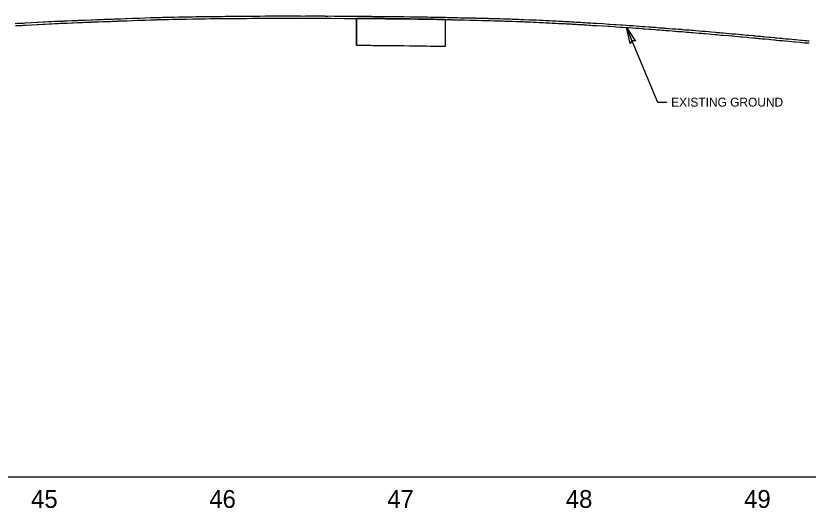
# Model space of a CAD drawing. Extents: x 2115752 to 2121174, y 562881 to 567245.
# Drawn here: x 2120180.3 to 2120624.7, y 566358.2 to 566634.2 of the extents above; entities that cross this region are included whole.
import ezdxf

# ---------------------------------------------------------------- set-up
doc = ezdxf.new("R2010")
doc.units = 0
for name, color, linetype in [('Exist Profile Cell', 7, 'Continuous'), ('Exist Vertical Profile Ground Line', 7, 'Continuous'), ('Exist Vertical Profile Horizontal Axis Label Major', 7, 'Continuous'), ('Prop Terminator CELL', 7, 'Continuous'), ('Prop VPI Label', 7, 'Continuous'), ('Prop XS Undercut Exc', 7, 'Continuous'), ('Prop XS Undercut Exc Hatch', 7, 'Continuous'), ('Scratch_Level_1', 7, 'Continuous')]:
    doc.layers.add(name, color=color, linetype=linetype)

msp = doc.modelspace()

# ---------------------------------------------------------------- linework, layer by layer
at = {"layer": 'Exist Profile Cell'}
msp.add_line((2116696.3, 566375.81), (2121174.42, 566375.81), dxfattribs=at)
at = {"layer": 'Exist Vertical Profile Ground Line'}
for points in [[(2120180.06, 566628.67), (2120181.26, 566628.75), (2120181.79, 566628.77), (2120182.24, 566628.8), (2120183.67, 566628.84), (2120184.47, 566628.91), (2120185.35, 566628.98), (2120185.71, 566629), (2120189.09, 566629.19), (2120192.3, 566629.36), (2120192.82, 566629.39), (2120195.67, 566629.54), (2120196.52, 566629.58), (2120198.92, 566629.7), (2120199.7, 566629.73), (2120200.22, 566629.76), (2120202.25, 566629.85), (2120203.11, 566629.89), (2120203.96, 566629.92), (2120205.58, 566629.98), (2120206.67, 566630.02), (2120207.31, 566630.06), (2120207.93, 566630.09), (2120209.06, 566630.13), (2120211.76, 566630.27), (2120212.38, 566630.29), (2120214.93, 566630.4), (2120215.74, 566630.44), (2120217.74, 566630.52), (2120219.2, 566630.57), (2120222.54, 566630.71), (2120222.91, 566630.73), (2120225.72, 566630.83), (2120226.17, 566630.85), (2120226.6, 566630.87), (2120229.03, 566630.95), (2120229.66, 566630.97), (2120230.35, 566631), (2120232.34, 566631.07), (2120233.18, 566631.09), (2120234.28, 566631.14), (2120235.66, 566631.19), (2120237.77, 566631.27), (2120238.08, 566631.29), (2120238.66, 566631.3), (2120239.1, 566631.32), (2120241.87, 566631.42), (2120242.47, 566631.44), (2120245.84, 566631.56), (2120248.68, 566631.67), (2120249.22, 566631.69), (2120253, 566631.8), (2120255.81, 566631.9), (2120256.18, 566631.92), (2120256.62, 566631.93), (2120259.27, 566632.02), (2120259.74, 566632.03), (2120260.62, 566632.06), (2120261.67, 566632.07), (2120262.5, 566632.11), (2120263.28, 566632.13), (2120264.26, 566632.15), (2120265.17, 566632.15), (2120265.89, 566632.18), (2120268.23, 566632.23), (2120269.18, 566632.24), (2120271.77, 566632.3), (2120272.65, 566632.31), (2120275.47, 566632.37), (2120276.03, 566632.37), (2120279.42, 566632.43), (2120281.29, 566632.47), (2120282.92, 566632.5), (2120283.46, 566632.5), (2120286.61, 566632.55), (2120289.41, 566632.59), (2120290.35, 566632.6), (2120291.08, 566632.6)], [(2120291.08, 566632.6), (2120292.84, 566632.61), (2120293.44, 566632.62), (2120294.07, 566632.62), (2120296.25, 566632.64), (2120297.8, 566632.65), (2120298.69, 566632.65), (2120299.53, 566632.65), (2120301.55, 566632.67), (2120302.96, 566632.67), (2120305.26, 566632.69), (2120306.31, 566632.7), (2120308.94, 566632.74), (2120309.71, 566632.75), (2120312.65, 566632.78), (2120313.11, 566632.79), (2120313.92, 566632.8), (2120316.47, 566632.82), (2120317.2, 566632.83), (2120320.13, 566632.85), (2120321.53, 566632.85), (2120323.21, 566632.85), (2120323.86, 566632.85), (2120326.57, 566632.85), (2120327.65, 566632.86), (2120329.15, 566632.87), (2120329.9, 566632.87), (2120331.36, 566632.92), (2120333.39, 566632.91), (2120335.14, 566632.87), (2120336.69, 566632.88), (2120338.87, 566632.88), (2120340.08, 566632.86), (2120341.2, 566632.83), (2120342.58, 566632.85), (2120343.5, 566632.86), (2120346.12, 566632.85), (2120346.91, 566632.85), (2120349.59, 566632.86), (2120350.24, 566632.87), (2120351.9, 566632.85), (2120353.42, 566632.84), (2120353.73, 566632.83), (2120355.33, 566632.79), (2120357.11, 566632.84), (2120358.83, 566632.76), (2120360.84, 566632.81), (2120362.38, 566632.74), (2120363.79, 566632.78), (2120364.72, 566632.77), (2120365.92, 566632.72), (2120367.11, 566632.75), (2120368.56, 566632.74), (2120369.52, 566632.7), (2120370.61, 566632.71), (2120372.28, 566632.69), (2120373.94, 566632.68), (2120376, 566632.68), (2120377.34, 566632.67), (2120379.7, 566632.65), (2120380.78, 566632.63), (2120381.96, 566632.6), (2120383.35, 566632.62), (2120384.25, 566632.62), (2120386.96, 566632.59), (2120387.55, 566632.58), (2120390.41, 566632.57), (2120390.94, 566632.56), (2120392.58, 566632.52), (2120394.36, 566632.53), (2120395.5, 566632.52), (2120397.98, 566632.49), (2120401.67, 566632.45), (2120403.07, 566632.38), (2120404.45, 566632.41), (2120405.63, 566632.4), (2120407.82, 566632.36), (2120409.36, 566632.34), (2120411.19, 566632.29), (2120413.06, 566632.25), (2120414.58, 566632.22), (2120416.78, 566632.2), (2120417.9, 566632.18), (2120420.47, 566632.12), (2120420.92, 566632.1), (2120421.33, 566632.1), (2120422.64, 566632.04), (2120424.2, 566632.03), (2120424.75, 566632.02), (2120426.14, 566631.96), (2120428.16, 566631.96), (2120429.67, 566631.88), (2120431.78, 566631.87), (2120434.81, 566631.78), (2120435.35, 566631.77), (2120438.18, 566631.72), (2120439.08, 566631.7), (2120441.6, 566631.63), (2120442.69, 566631.6), (2120445.01, 566631.54), (2120445.58, 566631.53)], [(2120445.58, 566631.53), (2120446.27, 566631.51), (2120448.43, 566631.44), (2120449.1, 566631.41), (2120449.98, 566631.41), (2120451.02, 566631.37), (2120451.86, 566631.38), (2120453.66, 566631.33), (2120454.5, 566631.28), (2120455.22, 566631.26), (2120457.47, 566631.2), (2120458.65, 566631.15), (2120461.11, 566631.07), (2120461.92, 566631.04), (2120463.41, 566630.91), (2120464.74, 566630.91), (2120465.35, 566630.89), (2120468.34, 566630.76), (2120468.75, 566630.74), (2120470.44, 566630.61), (2120472.1, 566630.6), (2120474, 566630.45), (2120475.82, 566630.42), (2120477.57, 566630.28), (2120479.19, 566630.26), (2120479.55, 566630.25), (2120481.09, 566630.12), (2120482.32, 566630.1), (2120482.7, 566630.08), (2120483.23, 566630.06), (2120484.61, 566629.96), (2120485.71, 566629.94), (2120486.29, 566629.91), (2120487.03, 566629.88), (2120488.15, 566629.8), (2120489.06, 566629.78), (2120489.83, 566629.72), (2120490.81, 566629.68), (2120491.75, 566629.61), (2120492.47, 566629.58), (2120493.38, 566629.51), (2120494.5, 566629.45), (2120495.29, 566629.39), (2120495.91, 566629.37), (2120496.93, 566629.3), (2120498.25, 566629.24), (2120498.83, 566629.19), (2120499.29, 566629.17), (2120500.45, 566629.05), (2120502.02, 566629.01), (2120502.66, 566628.97), (2120503.98, 566628.84), (2120505.99, 566628.76), (2120509.61, 566628.54), (2120512.75, 566628.33), (2120513.21, 566628.31), (2120516.14, 566628.12), (2120516.86, 566628.08), (2120519.51, 566627.88), (2120520.56, 566627.82), (2120522.89, 566627.66), (2120524.21, 566627.57), (2120526.27, 566627.43), (2120528.14, 566627.28), (2120529.68, 566627.17), (2120531.51, 566627.04), (2120532.33, 566626.95), (2120533.09, 566626.91), (2120535.3, 566626.75), (2120535.89, 566626.7), (2120536.45, 566626.66), (2120538.91, 566626.48), (2120539.81, 566626.41), (2120541.27, 566626.26), (2120542.6, 566626.19), (2120543.21, 566626.14), (2120543.65, 566626.1), (2120544.81, 566625.98), (2120546.48, 566625.9), (2120548.38, 566625.69), (2120549.97, 566625.62), (2120550.31, 566625.59), (2120551.4, 566625.47), (2120551.86, 566625.42), (2120553.33, 566625.36), (2120553.94, 566625.31), (2120555.37, 566625.15), (2120556.65, 566625.09), (2120557.84, 566624.99), (2120559.15, 566624.88), (2120560.04, 566624.81), (2120561.42, 566624.7), (2120563.41, 566624.53), (2120565.07, 566624.4), (2120565.95, 566624.3), (2120566.91, 566624.24), (2120568.95, 566624.07), (2120570.18, 566623.96), (2120572.55, 566623.76), (2120573.47, 566623.67), (2120574.75, 566623.53)], [(2120574.75, 566623.53), (2120576.15, 566623.43), (2120576.53, 566623.39), (2120576.88, 566623.36), (2120580.22, 566623.07), (2120581.94, 566622.93), (2120582.42, 566622.88), (2120583.72, 566622.77), (2120585.5, 566622.56), (2120586.86, 566622.47), (2120587.73, 566622.39), (2120590.26, 566622.17), (2120591.46, 566622.07), (2120593.66, 566621.85), (2120594.3, 566621.77), (2120595.16, 566621.71), (2120596.16, 566621.6), (2120597.01, 566621.54), (2120597.92, 566621.44), (2120598.96, 566621.37), (2120599.71, 566621.3), (2120600.38, 566621.24), (2120602.67, 566621.02), (2120603.79, 566620.91), (2120605.68, 566620.73), (2120606.27, 566620.67), (2120606.97, 566620.61), (2120608.46, 566620.42), (2120610.02, 566620.33), (2120610.35, 566620.3), (2120612.02, 566620.1), (2120613.83, 566619.98), (2120617.1, 566619.67), (2120617.58, 566619.63), (2120620.46, 566619.35), (2120621.26, 566619.28), (2120622.57, 566619.12), (2120623.85, 566619.03), (2120624.5, 566618.97), (2120625.07, 566618.92)]]:
    msp.add_lwpolyline(points, dxfattribs=at)
at = {"layer": 'Prop Terminator CELL'}
msp.add_lwpolyline([(2120524.92, 566618.75), (2120522.89, 566627.66), (2120527.85, 566619.92), (2120525.93, 566620.36)], close=True, dxfattribs=at)
at = {"layer": 'Prop VPI Label'}
msp.add_lwpolyline([(2120545.42, 566585.52), (2120540.45, 566585.52), (2120522.89, 566627.66)], dxfattribs=at)
at = {"layer": 'Prop XS Undercut Exc'}
for p, q in [((2120371.3, 566617.69), (2120371.3, 566632.7)), ((2120421.3, 566617.09), (2120421.3, 566632.1))]:
    msp.add_line(p, q, dxfattribs=at)
msp.add_lwpolyline([(2120371.3, 566617.69), (2120375.96, 566617.68), (2120377.23, 566617.67), (2120379.49, 566617.65), (2120380.45, 566617.63), (2120381.88, 566617.59), (2120383.49, 566617.62), (2120384.17, 566617.62), (2120386.8, 566617.59), (2120387.42, 566617.58), (2120390.29, 566617.57), (2120390.67, 566617.56), (2120392.44, 566617.52), (2120394.34, 566617.53), (2120395.33, 566617.52), (2120397.79, 566617.49), (2120401.22, 566617.45), (2120402.86, 566617.37), (2120404.55, 566617.4), (2120405.44, 566617.4), (2120407.6, 566617.36), (2120409.09, 566617.34), (2120410.84, 566617.3), (2120412.72, 566617.26), (2120414.32, 566617.22), (2120416.58, 566617.2), (2120417.6, 566617.18), (2120421.3, 566617.09)], dxfattribs=at)
at = {"layer": 'Prop XS Undercut Exc Hatch'}
for p, q in [((2120371.3, 566632.7), (2120371.3, 566617.69)), ((2120421.3, 566632.1), (2120420.92, 566632.1)), ((2120421.3, 566617.09), (2120421.3, 566632.1))]:
    msp.add_line(p, q, dxfattribs=at)
for points in [[(2120420.92, 566632.1), (2120420.47, 566632.12), (2120417.9, 566632.18), (2120416.78, 566632.2), (2120414.58, 566632.22), (2120413.06, 566632.25), (2120411.19, 566632.29), (2120409.36, 566632.34), (2120407.82, 566632.36), (2120405.63, 566632.4), (2120404.45, 566632.41), (2120403.07, 566632.38), (2120401.67, 566632.45), (2120397.98, 566632.49), (2120395.5, 566632.52), (2120394.36, 566632.53), (2120392.58, 566632.52), (2120390.94, 566632.56), (2120390.41, 566632.57), (2120387.55, 566632.58), (2120386.96, 566632.59), (2120384.25, 566632.62), (2120383.35, 566632.62), (2120381.96, 566632.6), (2120380.78, 566632.63), (2120379.7, 566632.65), (2120377.34, 566632.67), (2120376, 566632.68), (2120373.94, 566632.68), (2120372.28, 566632.69), (2120371.3, 566632.7)], [(2120371.3, 566617.69), (2120375.96, 566617.68), (2120377.23, 566617.67), (2120379.49, 566617.65), (2120380.45, 566617.63), (2120381.88, 566617.59), (2120383.49, 566617.62), (2120384.17, 566617.62), (2120386.8, 566617.59), (2120387.42, 566617.58), (2120390.29, 566617.57), (2120390.67, 566617.56), (2120392.44, 566617.52), (2120394.34, 566617.53), (2120395.33, 566617.52), (2120397.79, 566617.49), (2120401.22, 566617.45), (2120402.86, 566617.37), (2120404.55, 566617.4), (2120405.44, 566617.4), (2120407.6, 566617.36), (2120409.09, 566617.34), (2120410.84, 566617.3), (2120412.72, 566617.26), (2120414.32, 566617.22), (2120416.58, 566617.2), (2120417.6, 566617.18), (2120421.3, 566617.09)]]:
    msp.add_lwpolyline(points, dxfattribs=at)
at = {"layer": 'Scratch_Level_1'}
for points in [[(2120179.98, 566629.92), (2120181.21, 566630), (2120181.73, 566630.02), (2120182.17, 566630.05), (2120183.6, 566630.09), (2120184.37, 566630.15), (2120185.27, 566630.23), (2120185.64, 566630.25), (2120189.02, 566630.44), (2120192.23, 566630.61), (2120192.76, 566630.64), (2120195.6, 566630.78), (2120196.45, 566630.83), (2120198.86, 566630.94), (2120199.64, 566630.98), (2120200.16, 566631.01), (2120202.2, 566631.1), (2120203.06, 566631.14), (2120203.91, 566631.17), (2120205.54, 566631.23), (2120206.62, 566631.27), (2120207.25, 566631.3), (2120207.87, 566631.34), (2120209, 566631.38), (2120211.7, 566631.51), (2120212.32, 566631.54), (2120214.87, 566631.65), (2120215.69, 566631.69), (2120217.69, 566631.77), (2120219.15, 566631.82), (2120222.49, 566631.96), (2120222.87, 566631.98), (2120225.67, 566632.08), (2120226.12, 566632.1), (2120226.56, 566632.11), (2120228.98, 566632.2), (2120229.61, 566632.22), (2120230.29, 566632.25), (2120232.3, 566632.32), (2120233.14, 566632.34), (2120234.23, 566632.39), (2120235.61, 566632.44), (2120237.72, 566632.52), (2120238.05, 566632.53), (2120238.62, 566632.55), (2120239.04, 566632.57), (2120241.82, 566632.67), (2120242.43, 566632.69), (2120245.8, 566632.81), (2120248.64, 566632.92), (2120249.18, 566632.93), (2120252.96, 566633.04), (2120255.76, 566633.15), (2120256.13, 566633.17), (2120256.58, 566633.18), (2120259.23, 566633.27), (2120259.7, 566633.28), (2120260.59, 566633.31), (2120261.63, 566633.32), (2120262.46, 566633.36), (2120263.25, 566633.38), (2120264.25, 566633.4), (2120265.15, 566633.4), (2120265.85, 566633.43), (2120268.21, 566633.47), (2120269.15, 566633.49), (2120271.75, 566633.55), (2120272.62, 566633.56), (2120275.45, 566633.61), (2120276.01, 566633.62), (2120279.4, 566633.68), (2120281.26, 566633.72), (2120282.9, 566633.74), (2120283.44, 566633.75), (2120286.59, 566633.8), (2120289.39, 566633.84), (2120290.33, 566633.85), (2120291.07, 566633.85)], [(2120291.07, 566633.85), (2120292.83, 566633.86), (2120293.43, 566633.87), (2120294.06, 566633.87), (2120296.24, 566633.89), (2120297.8, 566633.9), (2120298.69, 566633.9), (2120299.52, 566633.9), (2120301.54, 566633.92), (2120302.96, 566633.92), (2120305.25, 566633.94), (2120306.29, 566633.95), (2120308.92, 566633.99), (2120309.7, 566634), (2120312.64, 566634.03), (2120313.1, 566634.04), (2120313.91, 566634.05), (2120316.46, 566634.07), (2120317.19, 566634.08), (2120320.12, 566634.1), (2120321.54, 566634.1), (2120323.21, 566634.1), (2120323.86, 566634.1), (2120326.56, 566634.1), (2120327.64, 566634.11), (2120329.14, 566634.12), (2120329.88, 566634.12), (2120331.35, 566634.17), (2120333.4, 566634.16), (2120335.15, 566634.12), (2120336.68, 566634.13), (2120338.88, 566634.13), (2120340.11, 566634.11), (2120341.21, 566634.08), (2120342.57, 566634.1), (2120343.5, 566634.11), (2120346.12, 566634.1), (2120346.91, 566634.1), (2120349.58, 566634.11), (2120350.24, 566634.12), (2120351.91, 566634.1), (2120353.43, 566634.09), (2120353.76, 566634.08), (2120355.33, 566634.04), (2120357.12, 566634.09), (2120358.84, 566634.01), (2120360.85, 566634.06), (2120362.39, 566633.99), (2120363.78, 566634.03), (2120364.75, 566634.02), (2120365.93, 566633.97), (2120367.1, 566634), (2120368.6, 566633.99), (2120369.54, 566633.95), (2120370.61, 566633.96), (2120372.29, 566633.94), (2120373.95, 566633.93), (2120376.01, 566633.93), (2120377.35, 566633.92), (2120379.72, 566633.9), (2120380.81, 566633.88), (2120381.97, 566633.85), (2120383.34, 566633.87), (2120384.26, 566633.87), (2120386.97, 566633.84), (2120387.56, 566633.83), (2120390.42, 566633.82), (2120390.96, 566633.81), (2120392.59, 566633.77), (2120394.36, 566633.78), (2120395.52, 566633.77), (2120398, 566633.74), (2120401.7, 566633.69), (2120403.09, 566633.63), (2120404.45, 566633.66), (2120405.65, 566633.65), (2120407.84, 566633.61), (2120409.39, 566633.59), (2120411.22, 566633.54), (2120413.08, 566633.5), (2120414.6, 566633.47), (2120416.8, 566633.45), (2120417.93, 566633.43), (2120420.52, 566633.37), (2120420.95, 566633.35), (2120421.35, 566633.35), (2120422.67, 566633.29), (2120424.21, 566633.28), (2120424.79, 566633.27), (2120426.17, 566633.21), (2120428.19, 566633.21), (2120429.71, 566633.13), (2120431.8, 566633.12), (2120434.84, 566633.03), (2120435.37, 566633.02), (2120438.21, 566632.97), (2120439.11, 566632.95), (2120441.63, 566632.88), (2120442.72, 566632.85), (2120445.05, 566632.79), (2120445.62, 566632.77)], [(2120445.61, 566632.77), (2120446.3, 566632.76), (2120448.48, 566632.69), (2120449.13, 566632.66), (2120450.01, 566632.66), (2120451.04, 566632.62), (2120451.87, 566632.63), (2120453.71, 566632.58), (2120454.55, 566632.53), (2120455.25, 566632.51), (2120457.52, 566632.45), (2120458.69, 566632.4), (2120461.16, 566632.32), (2120462, 566632.28), (2120463.46, 566632.16), (2120464.76, 566632.16), (2120465.4, 566632.14), (2120468.39, 566632.01), (2120468.82, 566631.99), (2120470.5, 566631.86), (2120472.16, 566631.85), (2120474.06, 566631.7), (2120475.88, 566631.67), (2120477.62, 566631.53), (2120479.22, 566631.51), (2120479.62, 566631.5), (2120481.16, 566631.37), (2120482.36, 566631.35), (2120482.77, 566631.33), (2120483.29, 566631.31), (2120484.66, 566631.21), (2120485.75, 566631.19), (2120486.35, 566631.16), (2120487.09, 566631.13), (2120488.22, 566631.05), (2120489.12, 566631.03), (2120489.9, 566630.97), (2120490.89, 566630.93), (2120491.82, 566630.86), (2120492.54, 566630.83), (2120493.46, 566630.76), (2120494.58, 566630.7), (2120495.35, 566630.64), (2120495.97, 566630.62), (2120497.01, 566630.55), (2120498.33, 566630.48), (2120498.91, 566630.44), (2120499.39, 566630.41), (2120500.53, 566630.3), (2120502.07, 566630.26), (2120502.76, 566630.22), (2120504.07, 566630.09), (2120506.05, 566630.01), (2120509.69, 566629.79), (2120512.83, 566629.58), (2120513.29, 566629.56), (2120516.22, 566629.37), (2120516.95, 566629.32), (2120519.59, 566629.13), (2120520.64, 566629.06), (2120522.97, 566628.9), (2120524.3, 566628.82), (2120526.37, 566628.67), (2120528.23, 566628.53), (2120529.77, 566628.42), (2120531.62, 566628.28), (2120532.43, 566628.2), (2120533.17, 566628.16), (2120535.4, 566627.99), (2120535.99, 566627.95), (2120536.55, 566627.91), (2120539, 566627.73), (2120539.92, 566627.66), (2120541.37, 566627.51), (2120542.69, 566627.44), (2120543.32, 566627.38), (2120543.77, 566627.34), (2120544.9, 566627.23), (2120546.58, 566627.15), (2120548.47, 566626.94), (2120550.05, 566626.87), (2120550.43, 566626.84), (2120551.54, 566626.71), (2120551.96, 566626.67), (2120553.4, 566626.61), (2120554.06, 566626.56), (2120555.47, 566626.39), (2120556.72, 566626.34), (2120557.94, 566626.24), (2120559.26, 566626.13), (2120560.14, 566626.06), (2120561.52, 566625.95), (2120563.51, 566625.78), (2120565.19, 566625.64), (2120566.06, 566625.55), (2120567, 566625.49), (2120569.06, 566625.32), (2120570.29, 566625.2), (2120572.66, 566625), (2120573.59, 566624.92), (2120574.89, 566624.77)], [(2120574.84, 566624.78), (2120576.26, 566624.67), (2120576.65, 566624.63), (2120576.98, 566624.61), (2120580.32, 566624.32), (2120582.05, 566624.17), (2120582.53, 566624.13), (2120583.85, 566624.01), (2120585.62, 566623.81), (2120586.96, 566623.72), (2120587.84, 566623.64), (2120590.37, 566623.42), (2120591.58, 566623.31), (2120593.8, 566623.09), (2120594.42, 566623.02), (2120595.27, 566622.96), (2120596.27, 566622.85), (2120597.12, 566622.79), (2120598.03, 566622.69), (2120599.06, 566622.62), (2120599.82, 566622.54), (2120600.49, 566622.49), (2120602.8, 566622.27), (2120603.91, 566622.15), (2120605.8, 566621.97), (2120606.39, 566621.91), (2120607.1, 566621.85), (2120608.58, 566621.67), (2120610.11, 566621.58), (2120610.49, 566621.54), (2120612.14, 566621.34), (2120613.93, 566621.22), (2120617.22, 566620.92), (2120617.7, 566620.87), (2120620.58, 566620.6), (2120621.39, 566620.52), (2120622.69, 566620.37), (2120623.95, 566620.28), (2120624.61, 566620.21), (2120625.2, 566620.17)]]:
    msp.add_lwpolyline(points, dxfattribs=at)

# ---------------------------------------------------------------- texts
at = {"layer": 'Exist Vertical Profile Horizontal Axis Label Major'}
for s, p in [('45', (2120188.85, 566358.31)), ('46', (2120288.79, 566358.31)), ('47', (2120388.65, 566358.31)), ('48', (2120488.77, 566358.31)), ('49', (2120588.81, 566358.31))]:
    msp.add_text(s, height=10, dxfattribs=at).set_placement(p)
at = {"layer": 'Prop VPI Label'}
msp.add_text('EXISTING GROUND', height=5, dxfattribs=at).set_placement((2120547.86, 566583.28))

doc.saveas('drawing.dxf')
